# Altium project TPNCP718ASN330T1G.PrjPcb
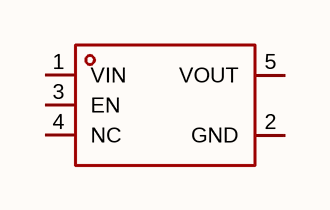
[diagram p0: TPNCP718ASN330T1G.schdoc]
1 sheet, 1 parts. Net scope: global (net labels, ports and power ports of the same name join across sheets).

## Sheet TPNCP718ASN330T1G.schdoc
size 127 x 101 mm

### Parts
U?  tpncp718asn330t1g  [SOT-23-5_L3.0-W1.6-P0.95-LS2.8-BR]  (value not drawn)

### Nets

Not connected (* = marked no-connect by the designer): U? 1(VIN) 2(GND) 3(EN) 4(NC) 5(VOUT)

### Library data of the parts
U? = tpncp718asn330t1g: 输出极性:正极;工作电压:24V;输出电压:3.3V;输出电流:300mA;电源纹波抑制比(PSRR):70dB@(1kHz);输出类型:固定;; Manufacturer: TECH PUBLIC(台舟); AddInBom: yes; ModelId: 72410e292833493f86746b22636ce101; ModelTransform: 110.236,116.1415,0,0,0,0,0.002,0.001,0; Output Configuration: 正极; Voltage - Supply: 24V; Output Voltage: 3.3V; Output Current: 300mA; Voltage Dropout: 420mV@(100mA); standby current: 4.5uA; Output Type: 固定; Number of Outputs: 1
